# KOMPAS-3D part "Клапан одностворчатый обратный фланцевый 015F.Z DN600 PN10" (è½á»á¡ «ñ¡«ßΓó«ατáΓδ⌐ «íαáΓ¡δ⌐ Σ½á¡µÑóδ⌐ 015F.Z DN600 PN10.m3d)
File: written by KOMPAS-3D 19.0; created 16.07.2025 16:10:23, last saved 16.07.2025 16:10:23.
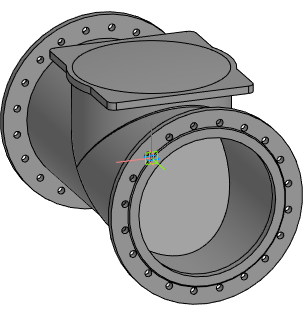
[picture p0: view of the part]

Document properties: Полное имя файла: E:\Dendor Работа Сачек\3D для проектировщиков\5.4 Тип 015F.Z. Клапан одностворчатый обратный фланцевый\stp_Клапан одностворчатый обратный фланцевый 015F.Z PN10_16\Клапан одностворчатый обратный фланцевый 015F.Z DN600 PN10.m3d

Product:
- Part/product: Клапан одностворчатый обратный фланцевый 015F.Z DN600 PN10

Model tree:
1. Операция без истории:1  (labels: Клапан одностворчатый обратный фланцевый 015F.Z DN600 PN10)
2. Операция без истории:2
